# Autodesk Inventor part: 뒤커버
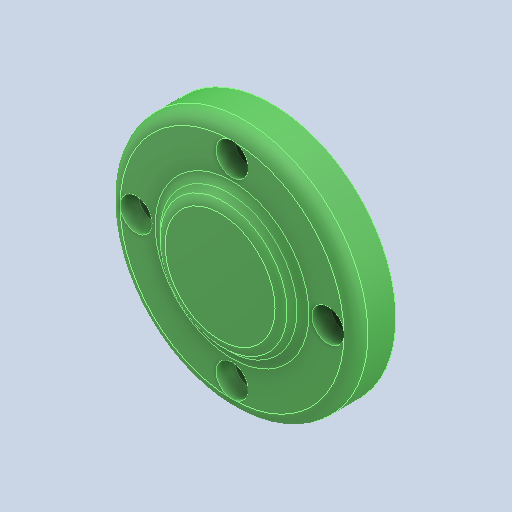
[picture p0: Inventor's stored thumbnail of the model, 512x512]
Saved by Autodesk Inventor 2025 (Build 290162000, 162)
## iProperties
Created: 2025-08
Part Number: 뒤커버
Material: 알루미늄 6061
Document SubType Name: Modeling
Designer: infra028
Density: 2.71 g/cm^3
Appearance: 기본값
Author: jhkim
Sending System: Autodesk Inventor 2026
Preprocessor: ST-DEVELOPER v20.1
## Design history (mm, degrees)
feature "솔리드1"
node "솔리드2"
